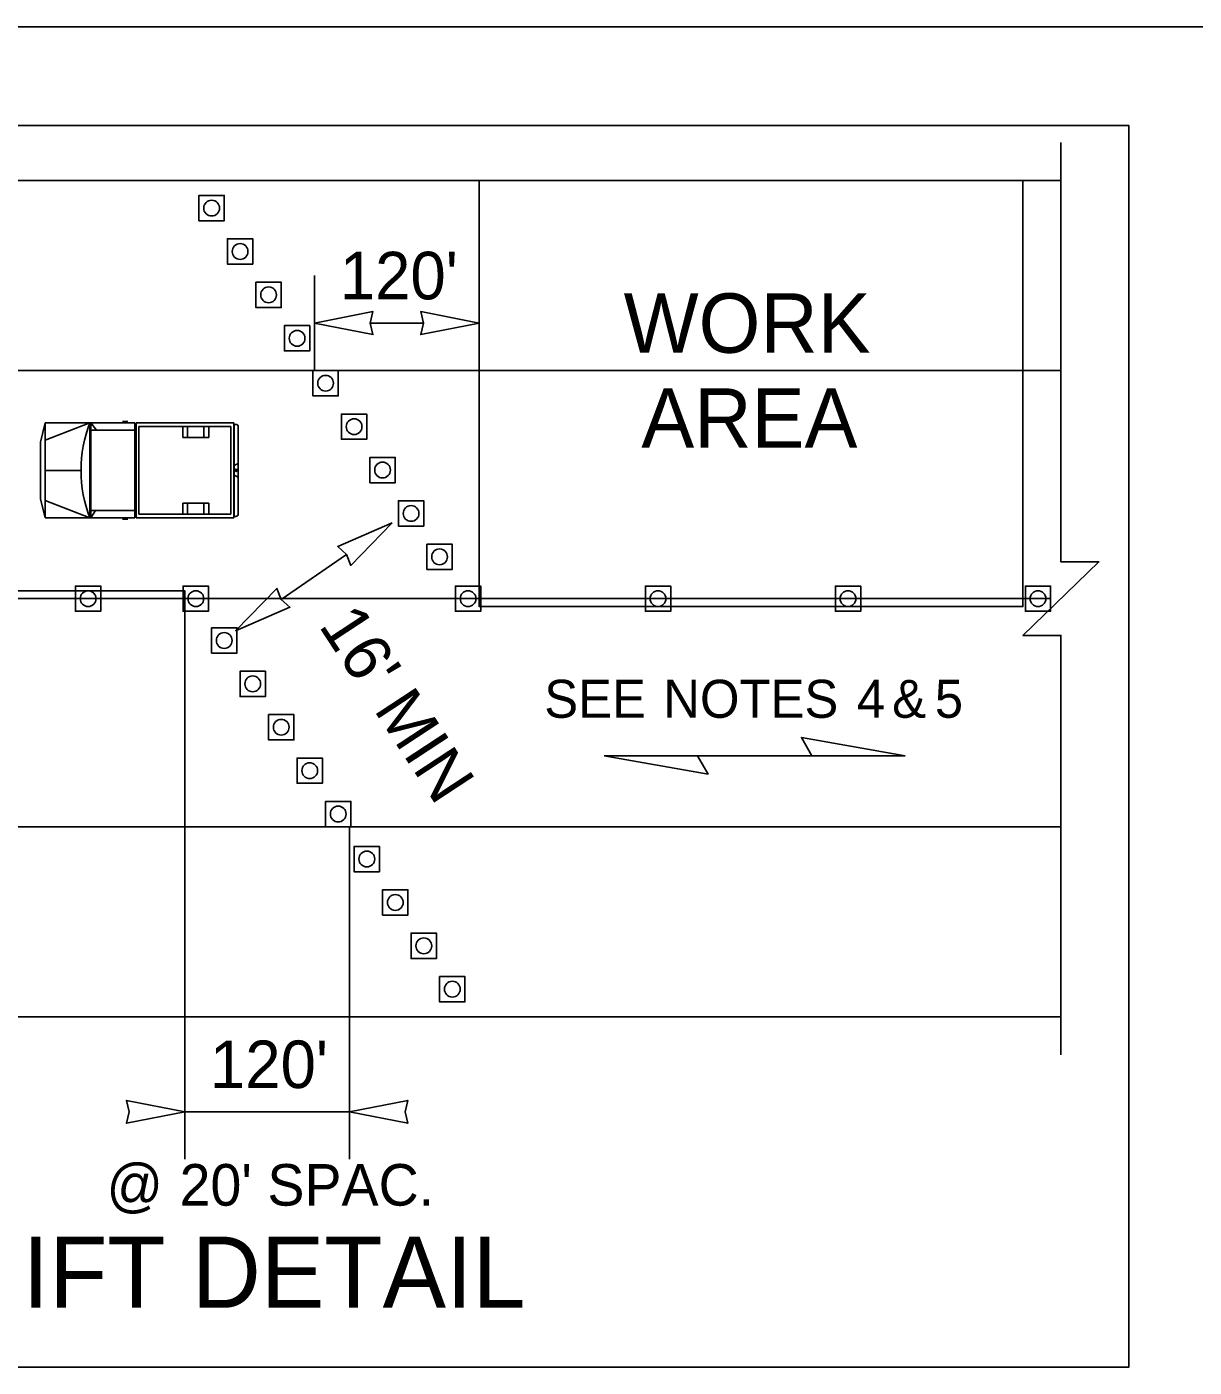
# Model space of a CAD drawing. Extents: x 99999.1 to 100095.7, y 99995 to 100010.7.
# Drawn here: x 100007.276 to 100009.243, y 100003.475 to 100005.732 of the extents above; entities that cross this region are included whole.
import ezdxf

# ---------------------------------------------------------------- set-up
doc = ezdxf.new("R2010")
doc.units = 0
for name, color, linetype in [('RD_ED_ShoulderPavedEdge', 7, 'Continuous'), ('RD_MK_LineEdgeWhite', 7, 'Continuous'), ('RD_MK_LineSkipCenter', 7, 'Continuous'), ('SH_DE_DetailHeading2Text', 7, 'Continuous'), ('SH_TI_Tables', 7, 'Continuous'), ('TR_WZ_MotoristVehicle', 7, 'Continuous'), ('TR_WZ_TrafficCone', 7, 'Continuous'), ('TR_WZ_WorkAreaLabel', 7, 'Continuous'), ('TR_WZ_WorkZoneDetails', 7, 'Continuous'), ('TR_WZ_WorkZoneTextCurrent', 7, 'Continuous')]:
    doc.layers.add(name, color=color, linetype=linetype)

msp = doc.modelspace()

# ---------------------------------------------------------------- linework, layer by layer
at = {"layer": 'RD_ED_ShoulderPavedEdge'}
for p, q in [((100000.1076, 100005.7323), (100015.6424, 100005.7323)), ((100005.1009, 100005.4735), (100009.0183, 100005.4735)), ((100005.1009, 100004.0655), (100009.0183, 100004.0655))]:
    msp.add_line(p, q, dxfattribs=at)
at = {"layer": 'RD_MK_LineEdgeWhite'}
for p, q in [((100005.1009, 100005.1535), (100009.0183, 100005.1535)), ((100005.1009, 100004.3855), (100009.0183, 100004.3855))]:
    msp.add_line(p, q, dxfattribs=at)
at = {"layer": 'RD_MK_LineSkipCenter'}
msp.add_lwpolyline([(100009.0017, 100004.7695), (100005.0844, 100004.7695)], dxfattribs=at)
at = {"layer": 'SH_TI_Tables'}
msp.add_lwpolyline([(100004.9869, 100005.5662), (100009.1323, 100005.5662), (100009.1323, 100003.4755), (100004.9869, 100003.4755)], close=True, dxfattribs=at)
at = {"layer": 'TR_WZ_MotoristVehicle'}
for p, q in [((100007.307, 100005.0655), (100007.2996, 100005.0332)), ((100007.307, 100005.0655), (100007.307, 100004.9055)), ((100007.307, 100005.0655), (100007.4581, 100005.0655)), ((100007.307, 100005.0362), (100007.3826, 100005.0655)), ((100007.3826, 100005.0655), (100007.3826, 100004.9055)), ((100007.384, 100005.0655), (100007.384, 100004.9055)), ((100007.384, 100005.0655), (100007.3936, 100005.0531)), ((100007.4375, 100005.0677), (100007.4466, 100005.0677)), ((100007.4581, 100005.0655), (100007.4581, 100004.9055)), ((100007.6249, 100005.0655), (100007.4603, 100005.0655)), ((100007.4603, 100005.0655), (100007.4603, 100004.9055)), ((100007.6202, 100005.0591), (100007.465, 100005.0591)), ((100007.465, 100005.0591), (100007.465, 100004.9119)), ((100007.5392, 100005.0591), (100007.5392, 100005.0407)), ((100007.5472, 100005.0591), (100007.5472, 100005.0407)), ((100007.5744, 100005.0591), (100007.5744, 100005.0407)), ((100007.5832, 100005.0591), (100007.5832, 100005.0407)), ((100007.6202, 100005.0591), (100007.6202, 100004.9119)), ((100007.6249, 100005.0655), (100007.6249, 100004.9055)), ((100007.629, 100005.0629), (100007.6255, 100005.0629)), ((100007.6255, 100005.0629), (100007.6255, 100004.9081)), ((100007.6326, 100005.058), (100007.6326, 100004.913)), ((100007.2996, 100005.0332), (100007.2996, 100004.9378)), ((100007.384, 100005.0531), (100007.4581, 100005.0531)), ((100007.5832, 100005.0407), (100007.5392, 100005.0407)), ((100007.6326, 100004.9968), (100007.6255, 100004.9938)), ((100007.629, 100004.9877), (100007.629, 100004.9832)), ((100007.307, 100004.9855), (100007.3677, 100004.9855)), ((100007.6326, 100004.9742), (100007.6255, 100004.9772)), ((100007.6307, 100004.9855), (100007.6274, 100004.9855)), ((100007.307, 100004.9055), (100007.2996, 100004.9378)), ((100007.307, 100004.9348), (100007.3826, 100004.9055)), ((100007.5392, 100004.9119), (100007.5392, 100004.9303)), ((100007.5832, 100004.9303), (100007.5392, 100004.9303)), ((100007.5472, 100004.9119), (100007.5472, 100004.9303)), ((100007.5744, 100004.9119), (100007.5744, 100004.9303)), ((100007.5832, 100004.9119), (100007.5832, 100004.9303)), ((100007.307, 100004.9055), (100007.4581, 100004.9055)), ((100007.384, 100004.9179), (100007.4581, 100004.9179)), ((100007.3919, 100004.9179), (100007.384, 100004.9055)), ((100007.4375, 100004.9032), (100007.4466, 100004.9032)), ((100007.6249, 100004.9055), (100007.4603, 100004.9055)), ((100007.6202, 100004.9119), (100007.465, 100004.9119)), ((100007.629, 100004.9081), (100007.6255, 100004.9081))]:
    msp.add_line(p, q, dxfattribs=at)
for centre, major_axis, start_param, end_param in [((100007.4906, 100004.9855), (0, -0.1679), 4.215667, 5.208926), ((100007.629, 100005.058), (0, 0.00488), 4.712389, 6.283185), ((100007.629, 100004.913), (0, -0.00488), 0, 1.570796)]:
    msp.add_ellipse(centre, major_axis=major_axis, ratio=0.73155, start_param=start_param, end_param=end_param, dxfattribs=at)
msp.add_ellipse((100007.629, 100004.9855), major_axis=(0, 0.00225), ratio=0.73155, dxfattribs=at)
at = {"layer": 'TR_WZ_TrafficCone'}
for points in [[(100007.5663, 100005.4484), (100007.6089, 100005.4484), (100007.6089, 100005.4058), (100007.5663, 100005.4058), (100007.5663, 100005.4484)], [(100007.5663, 100005.4058), (100007.6089, 100005.4058), (100007.6089, 100005.4484), (100007.5663, 100005.4484), (100007.5663, 100005.4058)], [(100007.6143, 100005.3754), (100007.6569, 100005.3754), (100007.6569, 100005.3327), (100007.6143, 100005.3327), (100007.6143, 100005.3754)], [(100007.6143, 100005.3327), (100007.6569, 100005.3327), (100007.6569, 100005.3754), (100007.6143, 100005.3754), (100007.6143, 100005.3327)], [(100007.6623, 100005.3023), (100007.7049, 100005.3023), (100007.7049, 100005.2596), (100007.6623, 100005.2596), (100007.6623, 100005.3023)], [(100007.6623, 100005.2596), (100007.7049, 100005.2596), (100007.7049, 100005.3023), (100007.6623, 100005.3023), (100007.6623, 100005.2596)], [(100007.7103, 100005.2292), (100007.7529, 100005.2292), (100007.7529, 100005.1866), (100007.7103, 100005.1866), (100007.7103, 100005.2292)], [(100007.7103, 100005.1866), (100007.7529, 100005.1866), (100007.7529, 100005.2292), (100007.7103, 100005.2292), (100007.7103, 100005.1866)], [(100007.7583, 100005.1535), (100007.801, 100005.1535), (100007.801, 100005.1108), (100007.7583, 100005.1108), (100007.7583, 100005.1535)], [(100007.7583, 100005.1108), (100007.801, 100005.1108), (100007.801, 100005.1535), (100007.7583, 100005.1535), (100007.7583, 100005.1108)], [(100007.8063, 100005.0804), (100007.849, 100005.0804), (100007.849, 100005.0378), (100007.8063, 100005.0378), (100007.8063, 100005.0804)], [(100007.8063, 100005.0378), (100007.849, 100005.0378), (100007.849, 100005.0804), (100007.8063, 100005.0804), (100007.8063, 100005.0378)], [(100007.8543, 100005.0074), (100007.897, 100005.0074), (100007.897, 100004.9647), (100007.8543, 100004.9647), (100007.8543, 100005.0074)], [(100007.8543, 100004.9647), (100007.897, 100004.9647), (100007.897, 100005.0074), (100007.8543, 100005.0074), (100007.8543, 100004.9647)], [(100007.9023, 100004.9343), (100007.945, 100004.9343), (100007.945, 100004.8916), (100007.9023, 100004.8916), (100007.9023, 100004.9343)], [(100007.9023, 100004.8916), (100007.945, 100004.8916), (100007.945, 100004.9343), (100007.9023, 100004.9343), (100007.9023, 100004.8916)], [(100007.9503, 100004.8612), (100007.993, 100004.8612), (100007.993, 100004.8186), (100007.9503, 100004.8186), (100007.9503, 100004.8612)], [(100007.9503, 100004.8186), (100007.993, 100004.8186), (100007.993, 100004.8612), (100007.9503, 100004.8612), (100007.9503, 100004.8186)], [(100007.3583, 100004.7908), (100007.4009, 100004.7908), (100007.4009, 100004.7482), (100007.3583, 100004.7482), (100007.3583, 100004.7908)], [(100007.3583, 100004.7482), (100007.4009, 100004.7482), (100007.4009, 100004.7908), (100007.3583, 100004.7908), (100007.3583, 100004.7482)], [(100007.5397, 100004.7908), (100007.5823, 100004.7908), (100007.5823, 100004.7482), (100007.5397, 100004.7482), (100007.5397, 100004.7908)], [(100007.5397, 100004.7482), (100007.5823, 100004.7482), (100007.5823, 100004.7908), (100007.5397, 100004.7908), (100007.5397, 100004.7482)], [(100008.0409, 100004.7908), (100007.9982, 100004.7908), (100007.9982, 100004.7482), (100008.0409, 100004.7482), (100008.0409, 100004.7908)], [(100008.0409, 100004.7482), (100007.9982, 100004.7482), (100007.9982, 100004.7908), (100008.0409, 100004.7908), (100008.0409, 100004.7482)], [(100008.3183, 100004.7908), (100008.3609, 100004.7908), (100008.3609, 100004.7482), (100008.3183, 100004.7482), (100008.3183, 100004.7908)], [(100008.3183, 100004.7482), (100008.3609, 100004.7482), (100008.3609, 100004.7908), (100008.3183, 100004.7908), (100008.3183, 100004.7482)], [(100008.6383, 100004.7908), (100008.6809, 100004.7908), (100008.6809, 100004.7482), (100008.6383, 100004.7482), (100008.6383, 100004.7908)], [(100008.6383, 100004.7482), (100008.6809, 100004.7482), (100008.6809, 100004.7908), (100008.6383, 100004.7908), (100008.6383, 100004.7482)], [(100008.9583, 100004.7908), (100009.0009, 100004.7908), (100009.0009, 100004.7482), (100008.9583, 100004.7482), (100008.9583, 100004.7908)], [(100008.9583, 100004.7482), (100009.0009, 100004.7482), (100009.0009, 100004.7908), (100008.9583, 100004.7908), (100008.9583, 100004.7482)], [(100007.6303, 100004.6778), (100007.5876, 100004.6778), (100007.5876, 100004.7204), (100007.6303, 100004.7204), (100007.6303, 100004.6778)], [(100007.6303, 100004.7204), (100007.5876, 100004.7204), (100007.5876, 100004.6778), (100007.6303, 100004.6778), (100007.6303, 100004.7204)], [(100007.6783, 100004.6047), (100007.6356, 100004.6047), (100007.6356, 100004.6474), (100007.6783, 100004.6474), (100007.6783, 100004.6047)], [(100007.6783, 100004.6474), (100007.6356, 100004.6474), (100007.6356, 100004.6047), (100007.6783, 100004.6047), (100007.6783, 100004.6474)], [(100007.7263, 100004.5316), (100007.6836, 100004.5316), (100007.6836, 100004.5743), (100007.7263, 100004.5743), (100007.7263, 100004.5316)], [(100007.7263, 100004.5743), (100007.6836, 100004.5743), (100007.6836, 100004.5316), (100007.7263, 100004.5316), (100007.7263, 100004.5743)], [(100007.7743, 100004.4586), (100007.7316, 100004.4586), (100007.7316, 100004.5012), (100007.7743, 100004.5012), (100007.7743, 100004.4586)], [(100007.7743, 100004.5012), (100007.7316, 100004.5012), (100007.7316, 100004.4586), (100007.7743, 100004.4586), (100007.7743, 100004.5012)], [(100007.8223, 100004.3855), (100007.7796, 100004.3855), (100007.7796, 100004.4282), (100007.8223, 100004.4282), (100007.8223, 100004.3855)], [(100007.8223, 100004.4282), (100007.7796, 100004.4282), (100007.7796, 100004.3855), (100007.8223, 100004.3855), (100007.8223, 100004.4282)], [(100007.8276, 100004.3524), (100007.8703, 100004.3524), (100007.8703, 100004.3098), (100007.8276, 100004.3098), (100007.8276, 100004.3524)], [(100007.8276, 100004.3098), (100007.8703, 100004.3098), (100007.8703, 100004.3524), (100007.8276, 100004.3524), (100007.8276, 100004.3098)], [(100007.8756, 100004.2794), (100007.9183, 100004.2794), (100007.9183, 100004.2367), (100007.8756, 100004.2367), (100007.8756, 100004.2794)], [(100007.8756, 100004.2367), (100007.9183, 100004.2367), (100007.9183, 100004.2794), (100007.8756, 100004.2794), (100007.8756, 100004.2367)], [(100007.9236, 100004.2063), (100007.9663, 100004.2063), (100007.9663, 100004.1636), (100007.9236, 100004.1636), (100007.9236, 100004.2063)], [(100007.9236, 100004.1636), (100007.9663, 100004.1636), (100007.9663, 100004.2063), (100007.9236, 100004.2063), (100007.9236, 100004.1636)], [(100007.9716, 100004.1332), (100008.0143, 100004.1332), (100008.0143, 100004.0906), (100007.9716, 100004.0906), (100007.9716, 100004.1332)], [(100007.9716, 100004.0906), (100008.0143, 100004.0906), (100008.0143, 100004.1332), (100007.9716, 100004.1332), (100007.9716, 100004.0906)]]:
    msp.add_lwpolyline(points, dxfattribs=at)
for centre in [(100007.5876, 100005.4271), (100007.6356, 100005.354), (100007.6836, 100005.281), (100007.7316, 100005.2079), (100007.7796, 100005.1322), (100007.8276, 100005.0591), (100007.8756, 100004.986), (100007.9236, 100004.913), (100007.9716, 100004.8399), (100007.3796, 100004.7695), (100007.561, 100004.7695), (100008.0196, 100004.7695), (100008.3396, 100004.7695), (100008.6596, 100004.7695), (100008.9796, 100004.7695), (100007.6089, 100004.6991), (100007.6569, 100004.626), (100007.7049, 100004.553), (100007.7529, 100004.4799), (100007.8009, 100004.4068), (100007.849, 100004.3311), (100007.897, 100004.258), (100007.945, 100004.185), (100007.993, 100004.1119)]:
    msp.add_circle(centre, 0.0133, dxfattribs=at)
at = {"layer": 'TR_WZ_WorkZoneDetails'}
for p, q in [((100007.7609, 100005.3135), (100007.7609, 100005.1535)), ((100008.0383, 100005.3135), (100008.0383, 100005.1535)), ((100007.8547, 100005.2335), (100007.9445, 100005.2335)), ((100007.8147, 100004.8438), (100007.7048, 100004.7682)), ((100008.406, 100004.5049), (100008.5989, 100004.5049)), ((100008.5989, 100004.5049), (100008.406, 100004.5049)), ((100007.8196, 100004.3855), (100007.8196, 100003.8255)), ((100007.5423, 100004.0655), (100007.5423, 100003.8255)), ((100007.5423, 100003.9055), (100007.8196, 100003.9055))]:
    msp.add_line(p, q, dxfattribs=at)
msp.add_lwpolyline([(100009.0183, 100004.0015), (100009.0183, 100004.7075), (100008.9542, 100004.7075), (100009.0823, 100004.8314), (100009.0183, 100004.8314), (100009.0183, 100005.5375)], dxfattribs=at)
for points in [[(100008.0383, 100005.4735), (100008.0383, 100004.7562), (100008.9542, 100004.7562), (100008.9542, 100005.4735)], [(100007.7609, 100005.2335), (100007.8592, 100005.2528), (100007.8547, 100005.2335), (100007.8592, 100005.2142)], [(100008.0383, 100005.2335), (100007.94, 100005.2528), (100007.9445, 100005.2335), (100007.94, 100005.2142)], [(100007.8919, 100004.897), (100007.8219, 100004.8254), (100007.8147, 100004.8438), (100007.8, 100004.8571)], [(100007.6276, 100004.7151), (100007.7195, 100004.7549), (100007.7048, 100004.7682), (100007.6977, 100004.7867)], [(100006.5639, 100004.7828), (100006.5639, 100004.0655), (100007.5423, 100004.0655), (100007.5423, 100004.7828)], [(100008.7561, 100004.5049), (100008.581, 100004.5358), (100008.5989, 100004.5049)], [(100008.2488, 100004.5049), (100008.4238, 100004.4741), (100008.406, 100004.5049)], [(100007.5423, 100003.9055), (100007.444, 100003.9248), (100007.4486, 100003.9055), (100007.444, 100003.8862)], [(100007.8196, 100003.9055), (100007.9179, 100003.9248), (100007.9134, 100003.9055), (100007.9179, 100003.8862)]]:
    msp.add_lwpolyline(points, close=True, dxfattribs=at)

# ---------------------------------------------------------------- texts
at = {"layer": 'SH_DE_DetailHeading2Text'}
msp.add_text('OPTIONAL LANE SHIFT DETAIL', height=0.12, rotation=360, dxfattribs=at).set_placement((100005.7267, 100003.5755))
at = {"layer": 'TR_WZ_WorkAreaLabel'}
for s, p in [('WORK', (100008.2817, 100005.1835)), ('AREA', (100008.3114, 100005.0235))]:
    msp.add_text(s, height=0.1, dxfattribs=at).set_placement(p)
at = {"layer": 'TR_WZ_WorkZoneTextCurrent'}
for s, height, rotation, p in [("120'", 0.08, 360, (100007.8035, 100005.2735)), ("16' MIN", 0.08, 303.3023, (100007.7668, 100004.7241)), ("120'", 0.08, 360, (100007.5848, 100003.9455)), ('@', 0.07, 360, (100007.4107, 100003.7475)), ("20' SPAC.", 0.07, 360, (100007.5336, 100003.7475))]:
    msp.add_text(s, height=height, rotation=rotation, dxfattribs=at).set_placement(p)
for s, p in [('SEE', (100008.1479, 100004.5689)), ('NOTES', (100008.3484, 100004.5689)), ('4', (100008.6744, 100004.5689)), ('&', (100008.7339, 100004.5689)), ('5', (100008.8058, 100004.5689))]:
    msp.add_text(s, height=0.064, dxfattribs=at).set_placement(p)

doc.saveas('drawing.dxf')
